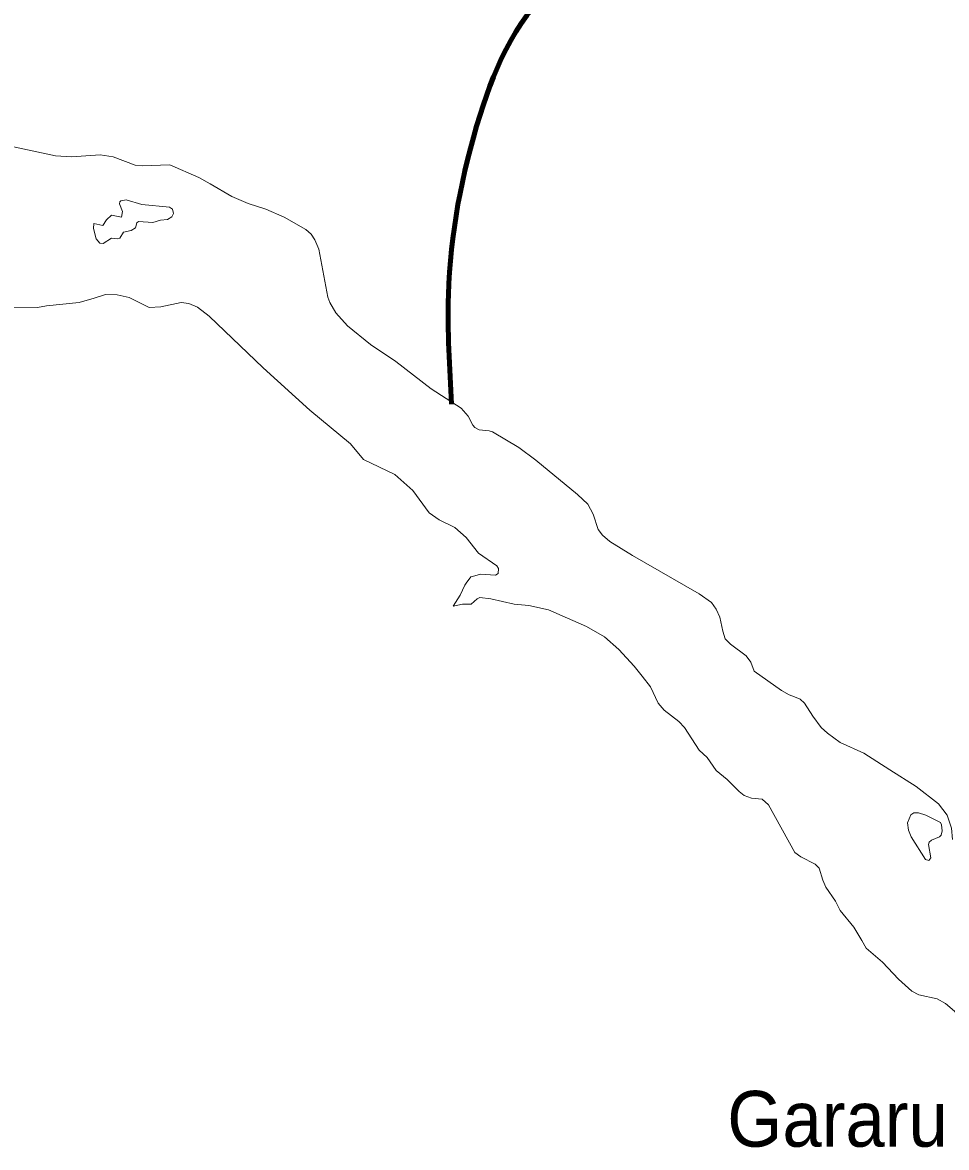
# Model space of a CAD drawing. Extents: x 553962 to 842807, y 8883888 to 9032388.
# Drawn here: x 701363 to 709644, y 8897106 to 8907189 of the extents above; entities that cross this region are included whole.
import ezdxf

# ---------------------------------------------------------------- set-up
doc = ezdxf.new("R2010")
doc.units = 0
doc.header["$LTSCALE"] = 200
doc.layers.add('25', color=7, linetype='Continuous', lineweight=13)
doc.layers.add('9', color=7, linetype='Continuous', lineweight=90)
doc.layers.add('41', color=7, linetype='Continuous')

msp = doc.modelspace()

# ---------------------------------------------------------------- linework, layer by layer
at = {"layer": '25'}
for points in [[(699730.1, 8905870.1), (699833.6, 8905937.4), (700049.1, 8906011), (700564.9, 8906093.9), (701005.2, 8906113.6), (701154.5, 8906101.4), (701659.8, 8905992.8), (701803.5, 8905986.5), (702058.9, 8906003.4), (702175.9, 8905983.8), (702373, 8905910.6), (702436.8, 8905905.5), (702682, 8905912.8), (702942.6, 8905799.8), (703043.5, 8905742.3)], [(703043.5, 8905742.3), (703240.1, 8905630.3), (703386.8, 8905567), (703544.9, 8905514.5)], [(703544.9, 8905514.5), (703544.9, 8905514.5), (703708.6, 8905443.2), (703903.3, 8905333.4), (703950.4, 8905293.2), (703983.7, 8905242.4), (704017.5, 8905157.8), (704100.5, 8904727.4), (704116.7, 8904678.1), (704169.6, 8904585.4), (704276.9, 8904471.4), (704483.1, 8904302.2), (704709.8, 8904149.5), (705025.3, 8903904.5), (705294.1, 8903731.4), (705355.9, 8903661.9), (705397.8, 8903579.9), (705416.3, 8903559.4), (705456.6, 8903537.1), (705545.2, 8903528.8), (705574.6, 8903518.8), (705812.1, 8903380.7), (705964.1, 8903265.1), (706335.8, 8902958.3), (706429, 8902870.5), (706478.4, 8902782.6), (706522.3, 8902644.6), (706561.4, 8902592.6), (706627.5, 8902537.3), (706829.4, 8902410.4), (707426.7, 8902069.6), (707536.7, 8901989.7), (707580.8, 8901930.1), (707613.5, 8901857.8), (707638, 8901734), (707661.4, 8901666.3), (707707.1, 8901616.1), (707849, 8901513.6), (707889.3, 8901456.4), (707921.2, 8901374.1), (708164.6, 8901203.2), (708234, 8901164.4), (708282.6, 8901144)], [(702004.3, 8904719), (701870.4, 8904678.1), (701577.9, 8904651), (701498, 8904635.9)], [(703520.5, 8904092.8), (703035.9, 8904557.4), (702930.4, 8904637.9), (702854, 8904670.9), (702784.7, 8904678.3), (702603.6, 8904639.4), (702499.6, 8904635.8), (702318.3, 8904724.9), (702212.1, 8904749.4), (702106.6, 8904750.3), (702004.3, 8904719)], [(701498, 8904635.9), (701073.3, 8904639.9), (700893.6, 8904612.2), (700683.7, 8904613.8), (700499, 8904578.5), (700435.5, 8904574.2), (700368.5, 8904593.8)], [(704418.9, 8903273.5), (704303.8, 8903412.4), (703938.7, 8903713.3), (703520.5, 8904092.8)], [(705417, 8902230.5), (705468.7, 8902243.1), (705601.7, 8902236.3), (705626.1, 8902249.9), (705630.1, 8902294), (705613.1, 8902318.7), (705450.5, 8902433.4), (705338.6, 8902571.8), (705237.8, 8902662.7), (705098.5, 8902732.8), (705008.4, 8902794.2), (704859.8, 8902995.3), (704700.7, 8903136.3), (704418.9, 8903273.5)], [(705340, 8902163.9), (705380.2, 8902221.5), (705417, 8902230.5)], [(705223.5, 8901956.6), (705285.9, 8902055.5), (705327.2, 8902145.4), (705340, 8902163.9), (705340, 8902163.9)], [(706917, 8901328.8), (706845.7, 8901419), (706706.3, 8901570.6), (706577.5, 8901683.7), (706418, 8901776), (706077.6, 8901924.8), (705902.1, 8901964.8), (705769.4, 8901975.3), (705559.8, 8902024.1), (705462.6, 8902034.1), (705436.9, 8902022.7), (705383.9, 8901976.1), (705305.7, 8901975.9), (705223.5, 8901956.6)], [(708884.8, 8898960.2), (708812.9, 8899081.1), (708692, 8899230.3), (708649.9, 8899313.3), (708562.2, 8899440.2), (708534.2, 8899502.9), (708503.8, 8899608.4), (708465.9, 8899644.1), (708336.8, 8899710.3), (708284.4, 8899750.1), (708047.8, 8900175.7), (707990.8, 8900226.5), (707897.1, 8900236.8), (707831, 8900260), (707784.3, 8900295.7), (707679.2, 8900403.7), (707579.3, 8900485.4), (707498.4, 8900600.3), (707426.9, 8900668.2), (707296.2, 8900870.2), (707244.9, 8900923.6), (707114.9, 8901025.9), (707060.8, 8901088.8), (706991.1, 8901234.8), (706917, 8901328.8)], [(708282.6, 8901144), (708331.2, 8901123.5), (708369.6, 8901088.6), (708444.9, 8900971.6), (708520.8, 8900871.2), (708577.2, 8900819.4), (708690.2, 8900735.5), (708901.9, 8900638.8), (709137.2, 8900490.7)], [(709137.2, 8900490.7), (709372.6, 8900342.6), (709571.9, 8900187.3), (709610.7, 8900136.5)], [(709610.7, 8900136.5), (709649.5, 8900085.8), (709687.8, 8899966.6), (709696.9, 8899867.4)], [(709950.2, 8897853.8), (709826.5, 8898078.7), (709765, 8898154.3), (709755.6, 8898257.5), (709714.4, 8898328.8), (709634.6, 8898396.5), (709559.8, 8898439.4), (709395, 8898473.4), (709333.8, 8898506.8), (709214.9, 8898614.3), (709070.8, 8898765.5), (708925, 8898892.5), (708884.8, 8898960.2)]]:
    msp.add_lwpolyline(points, dxfattribs=at)
for points in [[(702679.3, 8905532.6), (702433.7, 8905559), (702292.5, 8905598.5), (702244.4, 8905591.1), (702234.6, 8905581.9), (702232, 8905562.8), (702259.6, 8905493.7), (702249.4, 8905443.2), (702159.4, 8905461.2), (702115.8, 8905419.6), (702084.4, 8905369.4), (702001, 8905388), (701998, 8905341.8), (702023.2, 8905250.2), (702057, 8905211), (702086.6, 8905207.7), (702162.1, 8905255.6), (702214.5, 8905249.9), (702235, 8905255.7), (702269.6, 8905309.9), (702336.8, 8905325.8), (702376.9, 8905350), (702388.8, 8905392.2), (702403.4, 8905405.1), (702532.1, 8905397.2), (702600.3, 8905416.2), (702662.5, 8905423.3), (702700.1, 8905446), (702715.3, 8905477.1), (702706.1, 8905515.4)], [(709580.3, 8899889.8), (709596.2, 8899906.3), (709606, 8899943.5), (709599.7, 8899997.3), (709588.6, 8900017.3), (709459.5, 8900083.7), (709393.7, 8900104.9), (709351.6, 8900105.7), (709323, 8900086.1), (709294.9, 8900014.3), (709301.9, 8899949.1), (709327.1, 8899890.5), (709454.5, 8899688.2), (709485.7, 8899677.3), (709503.8, 8899701.2), (709483.4, 8899821.2), (709487.6, 8899841.5), (709510.1, 8899860.5)]]:
    msp.add_lwpolyline(points, close=True, dxfattribs=at)
at = {"layer": '9'}
msp.add_spline([(705207.9, 8903769.6), (705180.7, 8904747.4), (705463.8, 8906360), (706198.7, 8907564.6), (706955.5, 8908091.1), (707178.8, 8909156.3), (707379.5, 8909664.2), (707580.3, 8910146.8), (707959.3, 8910554.8), (708516.4, 8910888.1), (708891.3, 8912131.7), (709193.2, 8912716.3), (709242.2, 8913071.2)], degree=3, dxfattribs=at)

# ---------------------------------------------------------------- texts
at = {"layer": '41', "width": 0.95}
msp.add_text('Gararu', height=500, dxfattribs=at).set_placement((707678.8, 8897112.8))

doc.saveas('drawing.dxf')
